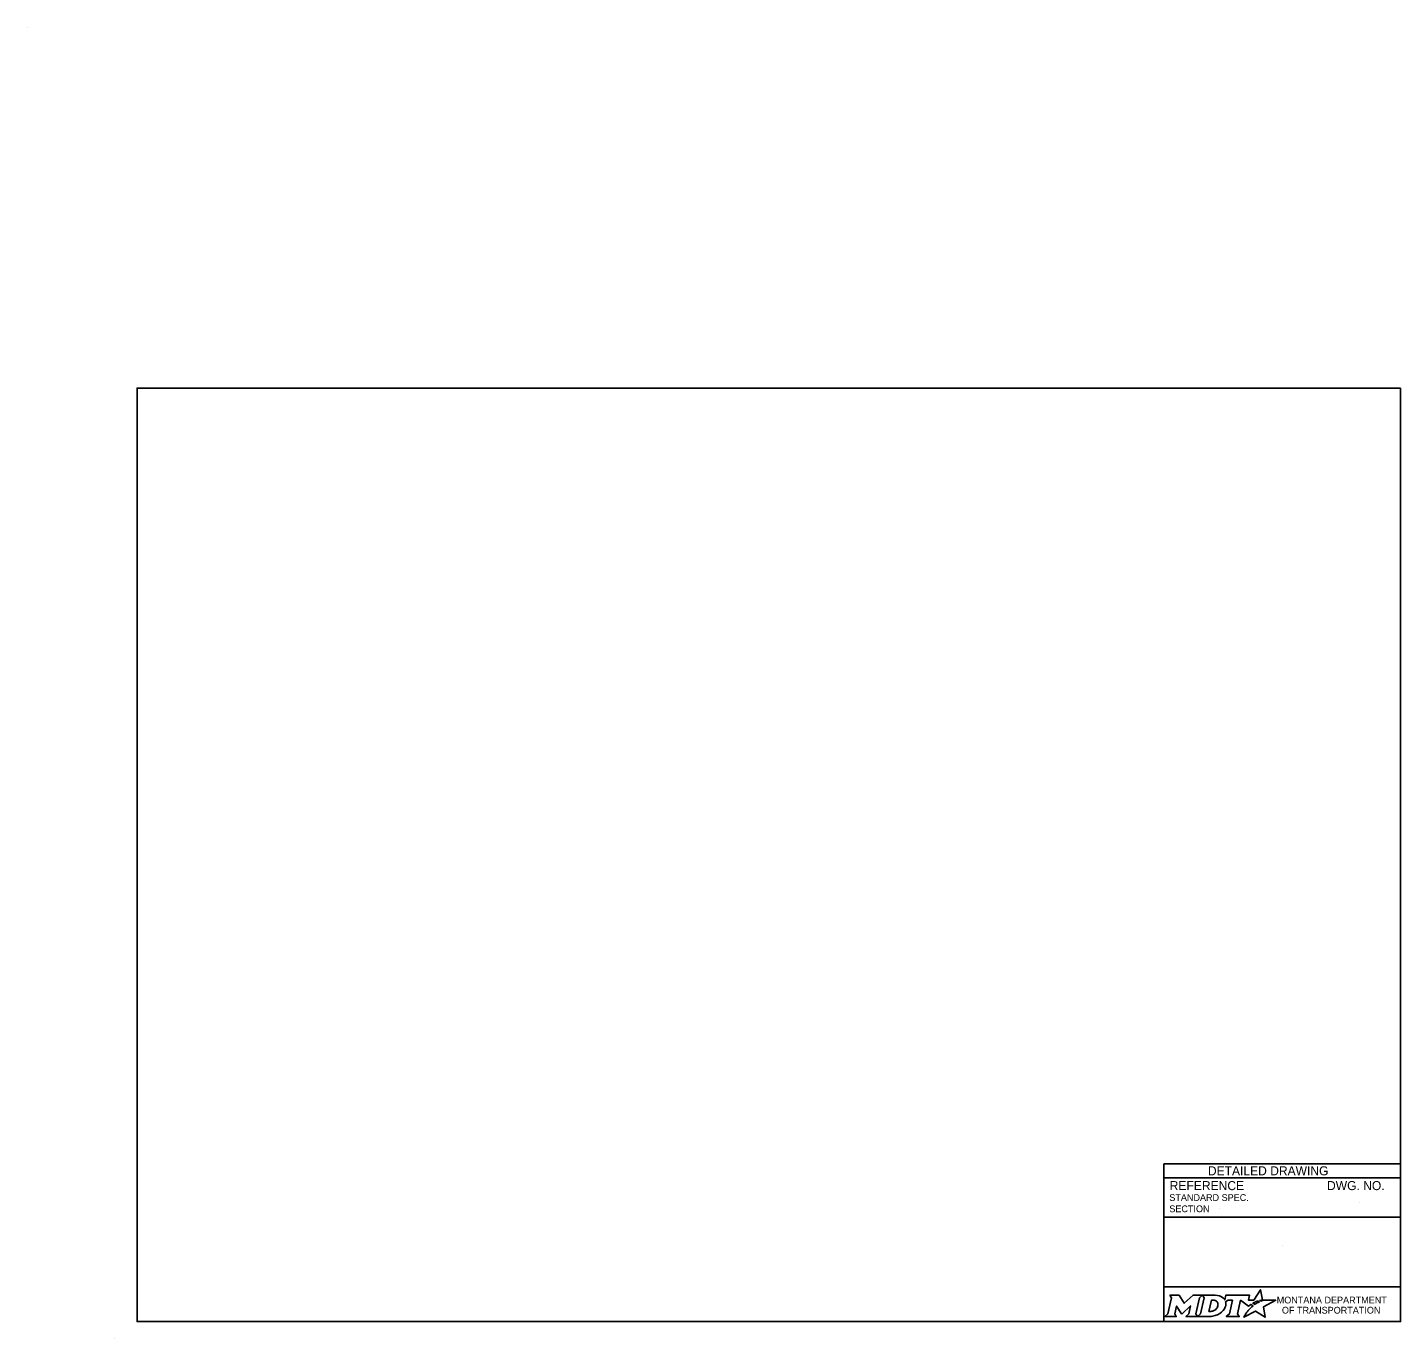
# Model space of a CAD drawing. Extents: x 49991.4 to 50043, y 49987.6 to 50011.4.
# Drawn here: x 50008.76 to 50020.94, y 49999.74 to 50011.36 of the extents above; entities that cross this region are included whole.
import ezdxf

# ---------------------------------------------------------------- set-up
doc = ezdxf.new("R2010")
doc.units = 0
for name, color, linetype in [('Default', 7, 'Continuous'), ('Level 1', 7, 'Continuous'), ('Level 4', 7, 'Continuous')]:
    doc.layers.add(name, color=color, linetype=linetype)

msp = doc.modelspace()

# ---------------------------------------------------------------- linework, layer by layer
at = {"layer": 'Default'}
for points in [[(50018.893, 50000.121), (50018.907, 50000.097), (50018.874, 49999.954), (50018.848, 49999.931), (50018.95, 49999.931), (50018.936, 49999.954), (50018.952, 50000.024), (50018.996, 49999.955), (50019.002, 49999.955), (50019.077, 50000.025), (50019.06, 49999.954), (50019.035, 49999.932), (50019.137, 49999.932), (50019.123, 49999.955), (50019.156, 50000.097)], [(50019.156, 50000.097), (50019.182, 50000.121), (50019.099, 50000.121), (50019.02, 50000.048), (50018.975, 50000.12), (50018.893, 50000.121)], [(50019.295, 50000.121), (50019.182, 50000.121), (50019.196, 50000.098), (50019.163, 49999.954), (50019.137, 49999.932), (50019.248, 49999.932)], [(50019.7, 50000.068), (50019.69, 50000.074), (50019.702, 50000.076), (50019.713, 50000.078), (50019.696, 50000.168), (50019.636, 50000.077), (50019.589, 50000.076), (50019.599, 50000.12), (50019.39, 50000.121), (50019.38, 50000.078), (50019.374, 50000.086)], [(50019.319, 50000.034), (50019.318, 50000.026), (50019.315, 50000.017), (50019.311, 50000.008), (50019.305, 50000.001), (50019.299, 49999.994), (50019.291, 49999.988), (50019.282, 49999.983), (50019.273, 49999.979), (50019.264, 49999.977), (50019.255, 49999.976), (50019.239, 49999.976), (50019.263, 50000.076), (50019.279, 50000.076), (50019.286, 50000.075), (50019.294, 50000.073), (50019.301, 50000.07), (50019.307, 50000.066), (50019.311, 50000.061), (50019.315, 50000.055), (50019.318, 50000.049), (50019.319, 50000.042), (50019.32, 50000.038), (50019.319, 50000.034)], [(50019.387, 50000.062), (50019.411, 50000.075), (50019.448, 50000.075), (50019.42, 49999.954), (50019.392, 49999.931), (50019.508, 49999.931), (50019.491, 49999.954), (50019.52, 50000.075), (50019.591, 50000.023), (50019.612, 50000.038), (50019.632, 50000.027)], [(50019.576, 49999.971), (50019.561, 49999.947), (50019.556, 49999.939), (50019.55, 49999.931), (50019.548, 49999.926), (50019.653, 49999.979), (50019.737, 49999.924), (50019.724, 50000.017), (50019.831, 50000.075), (50019.782, 50000.076), (50019.751, 50000.077), (50019.731, 50000.077), (50019.724, 50000.075), (50019.719, 50000.074), (50019.711, 50000.072), (50019.7, 50000.068)], [(50019.59, 49999.987), (50019.59, 49999.987)], [(50019.65, 50000.04), (50019.648, 50000.039), (50019.629, 50000.048), (50019.639, 50000.054), (50019.644, 50000.056), (50019.652, 50000.06), (50019.658, 50000.063), (50019.666, 50000.066), (50019.673, 50000.068), (50019.685, 50000.061), (50019.681, 50000.059), (50019.676, 50000.056), (50019.672, 50000.054), (50019.667, 50000.051), (50019.665, 50000.05), (50019.662, 50000.049), (50019.66, 50000.047), (50019.658, 50000.046), (50019.655, 50000.044), (50019.652, 50000.042), (50019.65, 50000.04)], [(50019.293, 49999.939), (50019.302, 49999.942), (50019.315, 49999.947), (50019.335, 49999.958)]]:
    msp.add_lwpolyline(points, dxfattribs=at)
for centre, radius, start, end in [((50019.274, 50000.059), 0.118, 300.9103, 339.1383), ((50019.319, 50000.042), 0.0709, 339.5329, 15.8582)]:
    msp.add_arc(centre, radius, start, end, dxfattribs=at)
for centre, major_axis, ratio, start_param, end_param in [((50019.293, 50000.073), (0.0834, -0.0037), 0.568097, 0.61298, 1.570796), ((50019.349, 50000.081), (0.0361, -0.0295), 0.469099, 1.225588, 1.570796), ((50019.583, 49999.979), (-0.00694, -0.00806), 0.008222, 0, 3.137361), ((50019.6, 49999.997), (-0.0098, -0.0102), 0.016458, 3.141593, 6.279097), ((50019.621, 50000.017), (-0.0112, -0.0097), 0.021651, 3.157348, 6.283185), ((50019.248, 50000.08), (0, 0.148), 0.987302, 3.139398, 3.456847)]:
    msp.add_ellipse(centre, major_axis=major_axis, ratio=ratio, start_param=start_param, end_param=end_param, dxfattribs=at)
at = {"layer": 'Level 1'}
for p, q in [((50008.765, 50011.363), (50008.765, 50011.363)), ((50009.537, 49999.736), (50009.537, 49999.736))]:
    msp.add_line(p, q, dxfattribs=at)
msp.add_lwpolyline([(50020.938, 50008.165), (50009.737, 50008.165), (50009.737, 49999.886), (50020.938, 49999.886)], close=True, dxfattribs=at)
at = {"layer": 'Level 4'}
for p, q in [((50020.938, 50001.286), (50018.838, 50001.286)), ((50018.838, 50001.286), (50018.838, 49999.886)), ((50020.938, 50001.161), (50018.838, 50001.161)), ((50020.574, 50000.946), (50020.574, 50000.946)), ((50020.938, 50000.811), (50018.838, 50000.811)), ((50019.332, 50000.886), (50019.332, 50000.886)), ((50019.888, 50000.562), (50019.888, 50000.562)), ((50020.938, 50000.193), (50018.838, 50000.193))]:
    msp.add_line(p, q, dxfattribs=at)

# ---------------------------------------------------------------- texts
at = {"layer": 'Default'}
for s, p in [('MONTANA DEPARTMENT', (50019.84, 50000.047)), ('OF TRANSPORTATION', (50019.886, 49999.957))]:
    msp.add_text(s, height=0.06, rotation=360, dxfattribs=at).set_placement(p)
at = {"layer": 'Level 4'}
for s, height, p in [('DETAILED DRAWING', 0.0799, (50019.23, 50001.183)), ('REFERENCE', 0.08, (50018.891, 50001.052)), ('DWG. NO.', 0.08, (50020.286, 50001.052)), ('STANDARD SPEC.', 0.06, (50018.888, 50000.956)), ('SECTION', 0.06, (50018.888, 50000.856))]:
    msp.add_text(s, height=height, dxfattribs=at).set_placement(p)

doc.saveas('drawing.dxf')
